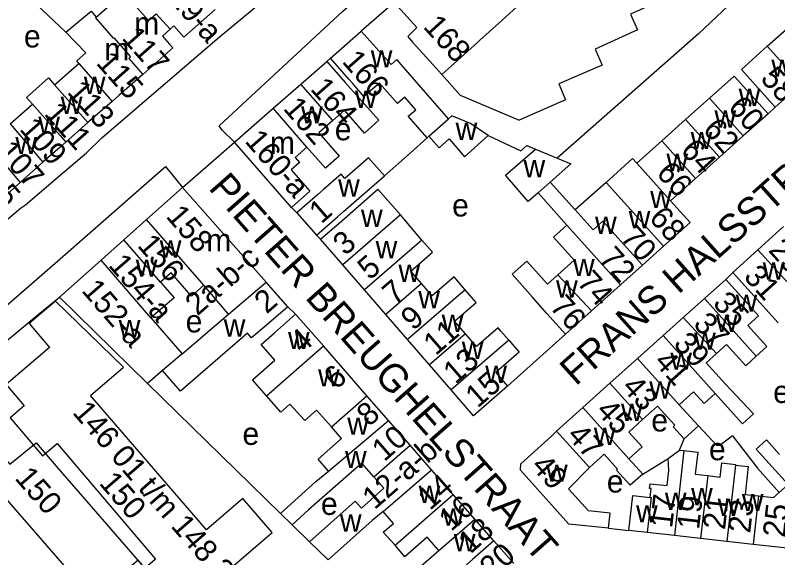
# Model space of a CAD drawing. Extents: x 161775 to 163181, y 382878 to 383925.
# Drawn here: x 162592 to 162727.8, y 383408.5 to 383505.2 of the extents above; entities that cross this region are included whole.
import ezdxf

# ---------------------------------------------------------------- set-up
doc = ezdxf.new("R2010")
doc.units = 0
for name, color, linetype in [('BLT_Basislijn', 7, 'Continuous'), ('BLT_Bebouwing', 7, 'Continuous'), ('BLT_Centroide', 7, 'Continuous'), ('BLT_Huisnummer', 7, 'Continuous'), ('BLT_Huisnummer_ tussenligend', 7, 'Continuous'), ('BLT_Huisnummer_reeks', 7, 'Continuous'), ('BLT_Huisnummer_zonder_bebouwing', 7, 'Continuous'), ('BLT_Onderverdeling_panden', 7, 'Continuous'), ('BLT_Plantopo', 7, 'Continuous'), ('BLT_Straatnaam', 7, 'Continuous'), ('BLT_Vlakafsluiter', 7, 'Continuous')]:
    doc.layers.add(name, color=color, linetype=linetype)

msp = doc.modelspace()

# ---------------------------------------------------------------- linework, layer by layer
at = {"layer": 'BLT_Basislijn'}
for p, q in [((162659.49, 383507.42), (162653.62, 383502.31)), ((162648.12, 383497.51), (162647.49, 383496.93)), ((162726.07, 383487.59), (162727.36, 383488.76)), ((162676.21, 383483.74), (162682.02, 383481.01)), ((162682.02, 383481.01), (162683.1, 383481.93)), ((162683.1, 383481.93), (162684.63, 383481.3)), ((162641.17, 383470.91), (162642.13, 383469.94)), ((162645.62, 383465.95), (162646.34, 383465.26)), ((162718.53, 383458.08), (162719.78, 383459.31)), ((162596.07, 383451.8), (162599.85, 383454.93)), ((162641.92, 383451.87), (162640.51, 383453.21)), ((162585.93, 383443.4), (162596.07, 383451.8)), ((162690.01, 383448.3), (162679.68, 383439.05)), ((162639.23, 383416.35), (162615.52, 383439.5)), ((162710.27, 383427.65), (162711.12, 383429.66)), ((162703.79, 383423.34), (162708.27, 383426.16)), ((162697.65, 383413.76), (162701.3, 383413.35))]:
    msp.add_line(p, q, dxfattribs=at)
for points in [[(162631.01, 383482.55), (162628.85, 383484.67), (162628.29, 383485.46), (162650.35, 383505.87), (162665.82, 383519.46), (162667.7, 383521.72), (162674.07, 383527.56), (162692.83, 383544.06), (162715.29, 383564.27), (162716.81, 383565.45), (162725.94, 383574.02)], [(162734.3, 383533.71), (162726.74, 383530.24), (162728, 383527.48), (162720.44, 383524.01), (162721.71, 383521.25), (162714.14, 383517.78), (162715.41, 383515.02), (162707.85, 383511.55), (162709.11, 383508.79), (162701.55, 383505.32), (162702.82, 383502.56), (162695.25, 383499.09), (162696.54, 383496.28), (162688.8, 383492.9), (162690.02, 383490.1), (162681.72, 383486.48)], [(162515.26, 383407.9), (162516.28, 383406.99), (162517.56, 383406.64), (162519.98, 383407.22), (162520.74, 383408.09), (162522.92, 383409.68), (162549.37, 383433.01), (162589.33, 383467.77), (162592.9, 383470.8), (162593.79, 383471.34), (162600, 383476.66), (162604.65, 383480.65), (162607.41, 383483.28), (162627.95, 383500.95), (162641.5, 383512.26), (162643.67, 383514.55), (162644.53, 383516.57), (162644.72, 383519.48), (162643.92, 383522.1)], [(162581.68, 383520.39), (162600, 383503.11), (162600.97, 383502.13)], [(162728.69, 383516.08), (162713.68, 383501.84), (162688.53, 383479.69)], [(162667.95, 383494.58), (162671.25, 383490.9), (162681.72, 383486.48)], [(162582.96, 383446.93), (162600, 383461.75), (162618.76, 383478.18), (162621.79, 383474.45)], [(162719.72, 383430.22), (162717.51, 383428.49), (162716.93, 383428.47), (162713.68, 383431.97)], [(162719.72, 383430.22), (162724.18, 383424.41), (162728.04, 383420.1)], [(162644.41, 383411.33), (162641.29, 383414.34)]]:
    msp.add_lwpolyline(points, dxfattribs=at)
at = {"layer": 'BLT_Bebouwing'}
for p, q in [((162627.6, 383506.18), (162622.03, 383501.24)), ((162678.06, 383503.68), (162681.35, 383506.64)), ((162674.76, 383500.71), (162678.06, 383503.68)), ((162725.94, 383499.63), (162730.41, 383503.64)), ((162620.04, 383499.33), (162614.68, 383494.61)), ((162721.32, 383495.48), (162725.94, 383499.63)), ((162671.42, 383497.7), (162667.95, 383494.58)), ((162642.85, 383492.88), (162647.49, 383496.93)), ((162727.36, 383488.76), (162721.32, 383495.48)), ((162614.68, 383494.61), (162610.43, 383490.86)), ((162715.63, 383490.37), (162720.03, 383494.32)), ((162720.03, 383494.32), (162726.07, 383487.59)), ((162637.92, 383488.58), (162642.85, 383492.88)), ((162669.17, 383486.71), (162663.88, 383492.76)), ((162731.98, 383492.91), (162727.36, 383488.76)), ((162610.43, 383490.86), (162609.21, 383489.78)), ((162609.21, 383489.78), (162604.92, 383486.01)), ((162711.39, 383486.56), (162715.63, 383490.37)), ((162591.04, 383485.78), (162595.05, 383489.31)), ((162631.01, 383482.55), (162637.92, 383488.58)), ((162669.75, 383487.23), (162669.17, 383486.71)), ((162673.05, 383485.88), (162669.75, 383487.23)), ((162726.07, 383487.59), (162721.67, 383483.65)), ((162604.92, 383486.01), (162601.01, 383482.55)), ((162676.21, 383483.74), (162673.05, 383485.88)), ((162707.15, 383482.76), (162711.39, 383486.56)), ((162665.34, 383483.33), (162662.35, 383480.55)), ((162665.34, 383483.33), (162665.64, 383483.62)), ((162665.64, 383483.62), (162667.49, 383481.53)), ((162667.49, 383481.53), (162669.26, 383483.1)), ((162669.26, 383483.1), (162672, 383479.93)), ((162672, 383479.93), (162676.21, 383483.74)), ((162702.69, 383478.77), (162707.15, 383482.76)), ((162721.67, 383483.65), (162717.43, 383479.84)), ((162641.17, 383470.91), (162631.01, 383482.55)), ((162679.3, 383476.63), (162684.63, 383481.3)), ((162684.63, 383481.3), (162688.53, 383479.69)), ((162662.35, 383480.55), (162657.72, 383476.51)), ((162596.91, 383478.94), (162592.82, 383475.33)), ((162654.9, 383479.74), (162657.72, 383476.51)), ((162690.96, 383478.68), (162687.27, 383475.42)), ((162688.53, 383479.69), (162690.96, 383478.68)), ((162717.43, 383479.84), (162713.16, 383476.06)), ((162713.16, 383476.06), (162708.71, 383472.07)), ((162592.82, 383475.33), (162588.72, 383471.72)), ((162691.74, 383470.45), (162687.27, 383475.42)), ((162697.21, 383475.36), (162691.74, 383470.45)), ((162621.79, 383474.45), (162615.36, 383468.74)), ((162636.65, 383457.59), (162621.79, 383474.45)), ((162685.1, 383473.51), (162690.25, 383467.77)), ((162708.71, 383472.07), (162712.17, 383468.19)), ((162664.4, 383465.07), (162660.57, 383469.56)), ((162615.36, 383468.74), (162611.33, 383465.14)), ((162712.17, 383468.19), (162707.42, 383463.98)), ((162724.28, 383463.35), (162728.85, 383467.48)), ((162611.33, 383465.14), (162607.26, 383461.52)), ((162707.42, 383463.98), (162703.71, 383460.6)), ((162719.78, 383459.31), (162724.28, 383463.35)), ((162607.26, 383461.52), (162599.85, 383454.93)), ((162654.18, 383456.21), (162650.32, 383460.67)), ((162703.71, 383460.6), (162699.81, 383457.12)), ((162629.98, 383451.9), (162625.55, 383457.02)), ((162640.51, 383453.21), (162636.65, 383457.59)), ((162699.81, 383457.12), (162694.65, 383452.49)), ((162718.53, 383458.08), (162714.74, 383454.67)), ((162657.98, 383451.83), (162654.18, 383456.21)), ((162714.74, 383454.67), (162710.97, 383451.29)), ((162621.7, 383444.83), (162629.98, 383451.9)), ((162646.87, 383446.21), (162641.92, 383451.87)), ((162661.85, 383447.36), (162657.98, 383451.83)), ((162694.65, 383452.49), (162690.01, 383448.3)), ((162616.15, 383451.24), (162621.7, 383444.83)), ((162710.97, 383451.29), (162707.39, 383448.07)), ((162665.78, 383442.83), (162661.85, 383447.36)), ((162707.39, 383448.07), (162702.84, 383443.97)), ((162654.63, 383437.34), (162646.87, 383446.21)), ((162702.84, 383443.97), (162697.9, 383439.57)), ((162669.64, 383438.38), (162665.78, 383442.83)), ((162618.21, 383441.85), (162615.52, 383439.5)), ((162697.9, 383439.57), (162693.09, 383435.25)), ((162673.62, 383433.79), (162669.64, 383438.38)), ((162679.68, 383439.05), (162673.62, 383433.79)), ((162658.47, 383432.94), (162654.63, 383437.34)), ((162693.09, 383435.25), (162688.39, 383431.02)), ((162710.26, 383435.74), (162713.68, 383431.97)), ((162648.28, 383431.79), (162645.66, 383434.78)), ((162662.32, 383428.55), (162658.47, 383432.94)), ((162713.68, 383431.97), (162711.12, 383429.66)), ((162666.15, 383424.16), (162662.32, 383428.55)), ((162708.27, 383426.16), (162710.27, 383427.65)), ((162710.27, 383427.65), (162711.09, 383427.56)), ((162701.3, 383426.1), (162703.79, 383423.34)), ((162670, 383419.75), (162666.15, 383424.16)), ((162673.84, 383415.37), (162670, 383419.75)), ((162724.39, 383419.48), (162727.05, 383419.19)), ((162677.25, 383411.46), (162673.84, 383415.37)), ((162704.53, 383412.99), (162701.3, 383413.35)), ((162709.38, 383412.44), (162704.53, 383412.99)), ((162714.06, 383411.91), (162709.38, 383412.44)), ((162647.72, 383408.1), (162644.41, 383411.33)), ((162680.77, 383407.44), (162677.25, 383411.46)), ((162718.73, 383411.38), (162714.06, 383411.91)), ((162723.41, 383410.85), (162718.73, 383411.38))]:
    msp.add_line(p, q, dxfattribs=at)
for points in [[(162606.39, 383504.83), (162611.3, 383509.18), (162612.03, 383508.36), (162615.7, 383504.22), (162617.05, 383505.41)], [(162659.49, 383507.42), (162663.53, 383502.94), (162661.88, 383501.38), (162662.76, 383500.38), (162665.21, 383497.65), (162667.95, 383494.58)], [(162600.97, 383502.13), (162605.48, 383505.85), (162606.39, 383504.83)], [(162622.03, 383501.24), (162620.24, 383503.25), (162619.57, 383502.65)], [(162604.55, 383498.44), (162600.97, 383502.13)], [(162619.57, 383502.65), (162618.19, 383501.42), (162619.45, 383500), (162620.04, 383499.33)], [(162648.12, 383497.51), (162653.62, 383502.31)], [(162663.88, 383492.76), (162659.97, 383497.25), (162658.95, 383496.35), (162653.62, 383502.31)], [(162674.76, 383500.71), (162674.4, 383500.38), (162671.42, 383497.7)], [(162603.3, 383496.57), (162602.92, 383497), (162604.55, 383498.44)], [(162598.97, 383492.76), (162603.3, 383496.57)], [(162647.49, 383496.93), (162650.77, 383493.16), (162653.15, 383490.43), (162656.72, 383486.44)], [(162665.34, 383483.33), (162661.99, 383487.17), (162663.31, 383488.32), (162661.36, 383490.56), (162660.04, 383489.41), (162656.84, 383493.07), (162654.07, 383490.65), (162652.02, 383493.05), (162651.41, 383493.75), (162648.12, 383497.51)], [(162595.05, 383489.31), (162593.99, 383490.51), (162597.9, 383493.97), (162598.97, 383492.76)], [(162656.72, 383486.44), (162654.2, 383484.14), (162650.64, 383488.22), (162648.52, 383486.38)], [(162648.52, 383486.38), (162646.03, 383484.2), (162649.66, 383480.04), (162647.22, 383477.91), (162643.94, 383481.67)], [(162601.01, 383482.55), (162600, 383481.66), (162596.91, 383478.94)], [(162643.94, 383481.67), (162641.81, 383479.82), (162642.6, 383478.91)], [(162642.6, 383478.91), (162641.13, 383477.62), (162644.47, 383473.79), (162641.17, 383470.91)], [(162654.9, 383479.74), (162650.67, 383476.05), (162650.01, 383476.81), (162646.88, 383474.09), (162645.9, 383473.23), (162642.13, 383469.94)], [(162702.69, 383478.77), (162701.94, 383479.6), (162697.21, 383475.36)], [(162645.62, 383465.95), (162649.38, 383469.24), (162650.43, 383470.15), (162657.72, 383476.51)], [(162685.1, 383473.51), (162683.37, 383471.98), (162679.3, 383476.63)], [(162646.34, 383465.26), (162650.12, 383468.53), (162656.59, 383474.14), (162660.57, 383469.56)], [(162642.13, 383469.94), (162645.62, 383465.95)], [(162690.25, 383467.77), (162687.84, 383465.6), (162691.53, 383461.49), (162688.61, 383458.87)], [(162650.32, 383460.67), (162646.34, 383465.26)], [(162664.33, 383457.34), (162662.42, 383459.54), (162666.29, 383462.9), (162664.4, 383465.07)], [(162690.01, 383448.3), (162686.67, 383452.02), (162684.1, 383454.89), (162680.51, 383459), (162683.09, 383461.31), (162686.77, 383457.22), (162688.61, 383458.87)], [(162625.55, 383457.02), (162623.34, 383455.1), (162619.76, 383459.23), (162617.87, 383457.59)], [(162672.09, 383456.24), (162670.13, 383458.51), (162666.24, 383455.14), (162664.33, 383457.34)], [(162727.85, 383450.36), (162719.78, 383459.31)], [(162617.87, 383457.59), (162620.26, 383454.79), (162616.15, 383451.24)], [(162723.98, 383444.39), (162725.86, 383446.09), (162722.47, 383449.86), (162724.38, 383451.58), (162721.87, 383454.36), (162718.53, 383458.08)], [(162672.17, 383448.37), (162670.2, 383450.64), (162674.05, 383453.98), (162672.09, 383456.24)], [(162599.85, 383454.93), (162606.1, 383448.77)], [(162640.51, 383453.21), (162636.73, 383449.94), (162634.08, 383447.65), (162633.35, 383448.49), (162621.41, 383438.16), (162618.21, 383441.85)], [(162636.72, 383437.32), (162634.21, 383440.19), (162638.19, 383443.68), (162635.75, 383446.47), (162638.16, 383448.58), (162641.92, 383451.87)], [(162606.1, 383448.77), (162615.52, 383439.5)], [(162679.88, 383447.26), (162678.48, 383448.88), (162677.99, 383449.43), (162674.14, 383446.1), (162672.17, 383448.37)], [(162679.88, 383447.26), (162681.75, 383445.1), (162677.58, 383441.48), (162679.68, 383439.05)], [(162723.98, 383444.39), (162722.1, 383442.7), (162718.69, 383446.49), (162716.88, 383444.86)], [(162716.88, 383444.86), (162715.07, 383443.23), (162718.5, 383439.41), (162723.5, 383434.12), (162721.52, 383432.35), (162716.66, 383437.76)], [(162716.66, 383437.76), (162714.67, 383435.97), (162712.81, 383438.03), (162710.26, 383435.74)], [(162640.9, 383435.82), (162639.29, 383434.41), (162636.72, 383437.32)], [(162640.9, 383435.82), (162643.53, 383432.92), (162645.66, 383434.78)], [(162711.12, 383429.66), (162709.19, 383431.81), (162709.48, 383432.07), (162706.4, 383435.49), (162703.72, 383433.08)], [(162583.88, 383433.41), (162591.02, 383425.16), (162595.68, 383428.96), (162600, 383423.97), (162604.73, 383418.5)], [(162703.72, 383433.08), (162701.26, 383430.87), (162703.65, 383428.21), (162701.3, 383426.1)], [(162647.75, 383423.93), (162645.91, 383426.04), (162650.1, 383429.71), (162648.28, 383431.79)], [(162697.65, 383413.76), (162690.59, 383414.47), (162681.95, 383424.09), (162682.01, 383425.2), (162687.5, 383430.14), (162688.39, 383431.02)], [(162728.04, 383420.1), (162729.63, 383421.54), (162723.98, 383427.84), (162725.79, 383429.46), (162728.1, 383426.89)], [(162711.09, 383427.56), (162713.54, 383427.28), (162713.1, 383423.36), (162715.33, 383423.1)], [(162703.79, 383423.34), (162701.49, 383421.42), (162699.1, 383424.08), (162699.28, 383424.24), (162696.88, 383426.92), (162694.25, 383424.56)], [(162705.1, 383419.22), (162705.28, 383420.8), (162704.96, 383420.84), (162705.06, 383421.67), (162708.09, 383421.33), (162708.39, 383424.04), (162708.27, 383426.16)], [(162655.85, 383422.9), (162653.72, 383425.33), (162644.23, 383417.03), (162641.29, 383414.34)], [(162697.65, 383413.76), (162697.95, 383416.39), (162694.11, 383416.81), (162690.55, 383420.77), (162694.25, 383424.56)], [(162715.33, 383423.1), (162717.53, 383422.85), (162717.82, 383425.38), (162720.29, 383425.1), (162720.27, 383424.98)], [(162720.27, 383424.98), (162722.54, 383424.73), (162721.97, 383419.75), (162724.39, 383419.48)], [(162639.23, 383416.35), (162645.54, 383422.07), (162647.75, 383423.93)], [(162657.64, 383420.85), (162655.85, 383422.9)], [(162609.66, 383396.77), (162600, 383407.9), (162590.12, 383419.29), (162589.48, 383418.74), (162587.25, 383421.31), (162579.44, 383414.56), (162563.18, 383400.54)], [(162653.63, 383417.33), (162657.64, 383420.85)], [(162701.3, 383413.35), (162702, 383419.57), (162705.1, 383419.22)], [(162727.05, 383419.19), (162728.04, 383420.1)], [(162604.73, 383418.5), (162614.84, 383406.83), (162614.6, 383406.62), (162617.36, 383403.43)], [(162644.41, 383411.33), (162652.54, 383418.56), (162653.63, 383417.33)], [(162641.29, 383414.34), (162639.23, 383416.35)], [(162657.49, 383416.73), (162655.58, 383415.1), (162647.72, 383408.1)], [(162659.63, 383410.69), (162657.52, 383413.03), (162659.33, 383414.58), (162657.49, 383416.73)], [(162733.92, 383413.54), (162730.08, 383410.09), (162723.41, 383410.85)], [(162667.43, 383409.77), (162665.37, 383412.12), (162661.38, 383408.63), (162659.63, 383410.69)], [(162670.88, 383405.89), (162670.16, 383406.72), (162666.89, 383403.86), (162665.09, 383405.92), (162662.94, 383404.04), (162662.05, 383405.06), (162667.43, 383409.77)]]:
    msp.add_lwpolyline(points, dxfattribs=at)
at = {"layer": 'BLT_Onderverdeling_panden'}
for p, q in [((162617.05, 383505.41), (162619.57, 383502.65)), ((162731.98, 383492.91), (162725.94, 383499.63)), ((162603.3, 383496.57), (162609.21, 383489.78)), ((162598.97, 383492.76), (162604.92, 383486.01)), ((162648.52, 383486.38), (162642.85, 383492.88)), ((162721.67, 383483.65), (162715.63, 383490.37)), ((162643.94, 383481.67), (162637.92, 383488.58)), ((162591.04, 383485.78), (162596.91, 383478.94)), ((162665.64, 383483.62), (162669.17, 383486.71)), ((162717.43, 383479.84), (162711.39, 383486.56)), ((162713.16, 383476.06), (162707.15, 383482.76)), ((162587.03, 383482.24), (162592.82, 383475.33)), ((162708.71, 383472.07), (162702.69, 383478.77)), ((162685.1, 383473.51), (162687.27, 383475.42)), ((162697.21, 383475.36), (162707.42, 383463.98)), ((162660.57, 383469.56), (162650.32, 383460.67)), ((162625.55, 383457.02), (162615.36, 383468.74)), ((162690.25, 383467.77), (162699.81, 383457.12)), ((162617.87, 383457.59), (162611.33, 383465.14)), ((162664.4, 383465.07), (162654.18, 383456.21)), ((162724.28, 383463.35), (162732.34, 383454.4)), ((162616.15, 383451.24), (162607.26, 383461.52)), ((162688.61, 383458.87), (162694.65, 383452.49)), ((162629.98, 383451.9), (162636.65, 383457.59)), ((162664.33, 383457.34), (162657.98, 383451.83)), ((162672.09, 383456.24), (162661.85, 383447.36)), ((162723.98, 383444.39), (162714.74, 383454.67)), ((162716.88, 383444.86), (162710.97, 383451.29)), ((162672.17, 383448.37), (162665.78, 383442.83)), ((162716.66, 383437.76), (162707.39, 383448.07)), ((162636.72, 383437.32), (162646.87, 383446.21)), ((162679.88, 383447.26), (162669.64, 383438.38)), ((162621.7, 383444.83), (162618.21, 383441.85)), ((162702.84, 383443.97), (162710.26, 383435.74)), ((162703.72, 383433.08), (162697.9, 383439.57)), ((162648.28, 383431.79), (162654.63, 383437.34)), ((162701.3, 383426.1), (162693.09, 383435.25)), ((162647.75, 383423.93), (162658.47, 383432.94)), ((162688.39, 383431.02), (162694.25, 383424.56)), ((162655.85, 383422.9), (162662.32, 383428.55)), ((162711.09, 383427.56), (162709.38, 383412.44)), ((162720.27, 383424.98), (162718.73, 383411.38)), ((162657.49, 383416.73), (162666.15, 383424.16)), ((162715.33, 383423.1), (162714.06, 383411.91)), ((162659.63, 383410.69), (162670, 383419.75)), ((162724.39, 383419.48), (162723.41, 383410.85)), ((162667.43, 383409.77), (162673.84, 383415.37))]:
    msp.add_line(p, q, dxfattribs=at)
for points in [[(162606.39, 383504.83), (162606.27, 383504.7), (162609.44, 383501.08), (162609.51, 383501.13), (162612.49, 383497.74), (162612.18, 383497.46), (162614.68, 383494.61)], [(162595.05, 383489.31), (162600, 383483.7), (162601.01, 383482.55)], [(162691.74, 383470.45), (162694.93, 383466.89), (162696.67, 383468.44), (162703.71, 383460.6)], [(162705.1, 383419.22), (162705.24, 383419.2), (162704.53, 383412.99)], [(162677.25, 383411.46), (162673.45, 383408.13), (162670.88, 383405.89)]]:
    msp.add_lwpolyline(points, dxfattribs=at)
at = {"layer": 'BLT_Plantopo'}
msp.add_lwpolyline([(162599.14, 383454.21), (162594.44, 383450.2), (162598.08, 383445.94), (162590.33, 383439.32), (162593.54, 383435.55), (162591.04, 383433.42), (162596.84, 383426.62), (162599.41, 383428.81), (162616.98, 383408.21), (162615.12, 383406.61), (162613.89, 383408.06), (162592.49, 383389.8), (162599.09, 383382.08), (162625.13, 383404.55), (162626.34, 383403.15), (162637.73, 383412.98), (162632.5, 383419.05), (162626.02, 383413.46), (162605.37, 383437.4), (162611.23, 383442.45)], close=True, dxfattribs=at)
at = {"layer": 'BLT_Vlakafsluiter'}
msp.add_line((162621.79, 383474.45), (162631.01, 383482.55), dxfattribs=at)

# ---------------------------------------------------------------- texts
at = {"layer": 'BLT_Centroide'}
for s, p in [('m', (162613.16, 383501.72)), ('e', (162593.52, 383499.41)), ('m', (162607.84, 383497.11)), ('w', (162655.3, 383495.84)), ('w', (162726.66, 383494.19)), ('w', (162604.19, 383491.14)), ('w', (162652.5, 383488.64)), ('w', (162720.84, 383488.98)), ('w', (162600.08, 383487.55)), ('w', (162642.89, 383485.86)), ('w', (162716.53, 383485.11)), ('w', (162596.08, 383484.03)), ('e', (162648.89, 383482.87)), ('w', (162670.41, 383482.93)), ('w', (162712.28, 383481.3)), ('w', (162591.98, 383480.41)), ('m', (162637.34, 383480.44)), ('w', (162707.97, 383477.42)), ('w', (162682.51, 383476.26)), ('w', (162649.48, 383472.84)), ('w', (162705.07, 383470.78)), ('e', (162669.8, 383469.29)), ('w', (162653.56, 383467.41)), ('w', (162695.25, 383466.19)), ('w', (162701.25, 383467.19)), ('w', (162617.71, 383461.94)), ('m', (162626, 383463.08)), ('w', (162656.17, 383461.84)), ('w', (162613.44, 383458.55)), ('w', (162691.33, 383458.66)), ('w', (162725.12, 383458.04)), ('w', (162660.23, 383457.62)), ('w', (162688.31, 383454.81)), ('w', (162663.77, 383452.94)), ('w', (162720.3, 383452.31)), ('e', (162622.33, 383448.63)), ('w', (162667.95, 383448.69)), ('w', (162716.78, 383448.69)), ('w', (162610.4, 383447.74)), ('w', (162629.11, 383447.88)), ('w', (162640.55, 383445.66)), ('w', (162712.91, 383445.53)), ('w', (162671.52, 383443.91)), ('w', (162708.67, 383441.97)), ('w', (162645.91, 383439)), ('w', (162675.7, 383439.61)), ('w', (162704.92, 383436.81)), ('e', (162726.99, 383436.05)), ('w', (162699.89, 383432.84)), ('e', (162705.28, 383430.97)), ('w', (162651.11, 383430.38)), ('e', (162632.45, 383428.58)), ('w', (162695.05, 383428.56)), ('e', (162715.55, 383425.85)), ('w', (162650.71, 383424.44)), ('w', (162686.52, 383422)), ('e', (162697.35, 383420.09)), ('w', (162663.83, 383418.23)), ('w', (162712.36, 383417.84)), ('e', (162646.43, 383416.1)), ('w', (162707.69, 383417)), ('w', (162717.11, 383415.92)), ('w', (162721.41, 383416.78)), ('w', (162702.56, 383414.76)), ('w', (162649.8, 383413.11)), ('w', (162668.07, 383414.19)), ('w', (162670.09, 383409.62))]:
    msp.add_text(s, height=4, dxfattribs=at).set_placement(p)
at = {"layer": 'BLT_Huisnummer'}
for s, rotation, p in [('119-a', 311.405, (162617.17, 383510.23)), ('117', 311.405, (162610.82, 383501)), ('166', 311.1173, (162650.04, 383496.83)), ('164', 311.0978, (162644.4, 383491.94)), ('113', 311.404, (162601.07, 383491.39)), ('60', 311.9151, (162718.76, 383488.59)), ('109', 311.404, (162592.58, 383484.78)), ('64', 311.9151, (162710.31, 383480.91)), ('105', 311.404, (162584.32, 383477.39)), ('66', 311.9151, (162706, 383476.89)), ('1', 40.9227, (162646.49, 383467.86)), ('68', 311.9057, (162704.7, 383468.88)), ('3', 40.9227, (162650.74, 383462.17)), ('156', 310.8851, (162613.58, 383464.05)), ('72', 311.9119, (162695.81, 383461.67)), ('31', 312.0094, (162721.57, 383458.45)), ('7', 40.9255, (162659.54, 383453.37)), ('2', 41.1951, (162636.75, 383451.81)), ('76', 311.9038, (162687.03, 383453.08)), ('37', 311.9599, (162712.58, 383450)), ('11', 40.9202, (162666.85, 383444.37)), ('4', 41.1951, (162643.06, 383444.74)), ('41', 311.9555, (162705.6, 383443.24)), ('15', 40.9255, (162674.33, 383435.03)), ('8', 41.193, (162654.97, 383431.7)), ('45', 312.5322, (162695.26, 383434.51)), ('49', 311.9563, (162683.7, 383424.69)), ('16', 41.1906, (162669.61, 383413.04)), ('17', 83.544, (162708.98, 383413.65)), ('21', 83.5444, (162718.4, 383413.35)), ('25', 83.5433, (162729.07, 383411.97)), ('20', 41.1892, (162676.88, 383404.54))]:
    msp.add_text(s, height=4, rotation=rotation, dxfattribs=at).set_placement(p)
at = {"layer": 'BLT_Huisnummer_ tussenligend'}
for s, rotation, p in [('115', 311.404, (162606.23, 383496.56)), ('58', 311.9104, (162724.56, 383493.75)), ('162', 311.1086, (162639.54, 383488.47)), ('111', 311.404, (162596.98, 383487.51)), ('62', 311.9151, (162714.28, 383484.64)), ('107', 311.404, (162588.53, 383480.68)), ('70', 311.9102, (162699.59, 383465.37)), ('29', 312.0126, (162725.99, 383463.18)), ('5', 40.9255, (162655.12, 383457.81)), ('74', 311.9045, (162691.87, 383457.42)), ('35', 311.9599, (162716.06, 383453.69)), ('9', 40.9202, (162662.84, 383448.81)), ('39', 311.9555, (162709.05, 383446.47)), ('13', 40.9202, (162670.38, 383439.28)), ('6', 41.193, (162649.1, 383438.27)), ('43', 312.5322, (162699.85, 383438.72)), ('10', 41.1947, (162657.7, 383425.47)), ('47', 312.5322, (162690.08, 383430.12)), ('14', 41.1906, (162665.85, 383416.79)), ('19', 83.544, (162713.78, 383413.39)), ('23', 83.5444, (162722.89, 383412.74)), ('18', 41.1892, (162673.05, 383409.03))]:
    msp.add_text(s, height=4, rotation=rotation, dxfattribs=at).set_placement(p)
at = {"layer": 'BLT_Huisnummer_reeks'}
for s, rotation, p in [('168', 312.0905, (162664.48, 383503.03)), ('160-a', 311.1086, (162632.71, 383482.65)), ('158', 310.9971, (162618.67, 383469.24)), ('154-a', 310.8851, (162608.42, 383460.53)), ('2a-b-c', 41.1933, (162624.43, 383451.46)), ('152-a', 310.8851, (162603.64, 383456.02)), ('12-a-b', 41.1947, (162655.98, 383416.91)), ('150', 310.8886, (162591.75, 383422.58))]:
    msp.add_text(s, height=4, rotation=rotation, dxfattribs=at).set_placement(p)
at = {"layer": 'BLT_Huisnummer_zonder_bebouwing'}
for s, p in [('146 01 t/m 148 29', (162602.02, 383434.29)), ('150', (162606.75, 383421.71))]:
    msp.add_text(s, height=4, rotation=310.8886, dxfattribs=at).set_placement(p)
at = {"layer": 'BLT_Straatnaam'}
for s, rotation, p in [('FRANS HALSSTRAAT', 41.8155, (162691.82, 383438.95)), ('PIETER BREUGHELSTRAAT', 311.4152, (162626.26, 383474.28))]:
    msp.add_text(s, height=5, rotation=rotation, dxfattribs=at).set_placement(p)

doc.saveas('drawing.dxf')
